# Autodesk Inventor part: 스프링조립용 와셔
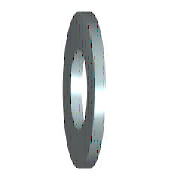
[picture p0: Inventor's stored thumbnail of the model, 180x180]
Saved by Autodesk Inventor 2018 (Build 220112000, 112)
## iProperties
IsCustomPart: 1
Created: 2012-02
Part Number: 스프링조립용 와셔
Material: 강철, 연강
Description: 평면 와셔
Document SubType Name: Modeling
Standard: KS B 1326
Designer: mduedu
Standards Organization: KS
Language: ko-KR
Size Designation: 12x24
Categories: <MemberInstance><Categories><Category DisplayName="조임쇠" InternalName="e4da775c-781d-43d5-af7c-5136215cf5a6" Mnemonic="FSTN"><Category DisplayName="와셔" InternalN
Density: 7.85 g/cm^3
Appearance: 강철
Mass: 5.38854 g
Surface Area: 8.71478 cm^2
Volume: 0.686438 cm^3
Author: mduedu
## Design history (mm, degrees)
sketch "스케치"
  geometry: C1 r 12 at (0, 0); C2 r 7 at (0, 0); 1 further point
  constraints: 2 centre point, 2 coincident
  dimensions: "d0" = 14 diameter of C2 (= SD1); "d1" = 24 diameter of C1 (= SD2)
extrude "본체" new body sketch "스케치" distance "d2" = 2.3 (= SD); taper "d3" = 0 deg
workaxis "Work Axis1"
workplane "Work Plane1"
body "Solid1"
other parameters: "SD1" = 14 [user parameter; used in 1 equation term], "SD2" = 24 [user parameter; used in 1 equation term], "SD" = 2.3 [user parameter; used in 1 equation term], "d4" = 0, "d5" = 0, "d6" = 0, "d7" = 0, "NND" = 12 [user parameter]
